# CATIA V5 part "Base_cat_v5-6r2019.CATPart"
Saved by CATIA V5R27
Part number: Base
Bounding box of the stored display mesh (mm): x -32 to 32, y 0 to 144, z 0 to 52
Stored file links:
  E:\_Deepak\2017_Deepak\CATIA\Resources\Tutorial Files\Tutorials\c16_catia_v5_6r2016_tut\Bench vice\Base_cat_v5-6r2016.CATPart
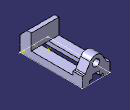
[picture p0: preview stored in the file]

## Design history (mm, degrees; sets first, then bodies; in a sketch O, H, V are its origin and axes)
Body1 (main body)
  Sketch1 on xy-plane, origin (0, 0, 0), H (1, 0, 0), V (0, 1, 0)
    point P1 (-32, 0)
    line L1 (-32, 0) -> (32, 0)
    line L2 (32, 0) -> (32, 144)
    line L3 (32, 144) -> (-32, 144)
    line L4 (-32, 144) -> (-32, 0)
    length L1 = 64
    length L2 = 144
    distance V L2 = 32
    coincidence: P1 H
    horizontal: L1 H, L3 H
    vertical: L2 V, L4 V
  Pad1: profile Sketch1, direction (0, 0, 1), length 16
  Sketch2 on face of Pad1, origin (32, 0, 0), H (0, 1, 0), V (0, 0, 1)
    point P1 (0, 16)
    line L1 (0, 16) -> (0, 36)
    point P2 (0, 36)
    line L2 (26, 52) -> (26, 16)
    line L3 (26, 16) -> (0, 16)
    reference projected line E1 (144, 16) -> (0, 16) from edge of Pad1
    line L4 (26, 52) -> (16, 52)
    point P5 (16, 52)
    line L5 (16, 52) -> (0, 36)
    length L2 = 36
    distance P5 P2 H = 16
    distance P5 P2 V = 16
    length L3 = 26
    coincidence: P1 V, E1 L3
    vertical: L1 V, L2 V
    horizontal: L3 H, L4 H
  Pad2: profile Sketch2, direction (-1, 0, 0), length 64
  Sketch3 on face of Pad1, origin (0, 144, 0), H (-1, 0, 0), V (0, 0, 1)
    line L1 (-32, 16) -> (-32, 24)
    point P2 (32, 24)
    line L2 (32, 24) -> (32, 16)
    line L3 (32, 16) -> (-32, 16)
    reference projected line E1 (32, 16) -> (-32, 16) from edge of Pad1
    line L4 (32, 24) -> (26, 24)
    point P4 (26, 24)
    line L5 (26, 24) -> (13.6777, 44.3018)
    point P5 (0, 52)
    line L6 (-13.6777, 44.3018) -> (-26, 24)
    point P6 (-26, 24)
    line L7 (-26, 24) -> (-32, 24)
    reference projected line E2 (32, 52) -> (-32, 52) from edge of Pad2
    reference projected line E3 (32, 16) -> (32, 52) from edge of Pad2
    reference projected line E4 (-32, 0) -> (-32, 16) from edge of Pad1
    arc A1 centre (0, 36) radius 16 from (13.6777, 44.3018) to (-13.6777, 44.3018) ccw
    point P8 (0, 36)
    reference projected line E5 (32, 52) -> (-32, 52) from edge of Pad2
    circle A2 centre (0, 36) radius 8
    distance H P2 = 24
    distance P6 P4 = 52
    distance P6 V = 26
    radius A1 = 16
    radius A2 = 8
    vertical: L1 V, L2 V
    horizontal: L3 H, L4 H, L7 H
    coincidence: L3 E1, P5 V, P6 L4, P5 E2, L2 E3, L1 E4, P8 V
    tangency: A1 E5, L6 A1, A1 L5
  Pad3: profile Sketch3, direction (0, -1, 0), length 22
  Fillet1: radius 3, on 2 edges
  Sketch4 on face of Pad1, origin (0, 144, 0), H (-1, 0, 0), V (0, 0, 1)
    point P1 (-16, 0)
    line L1 (-16, 0) -> (-16, 7)
    point P2 (-16, 7)
    line L2 (-16, 7) -> (-8, 7)
    point P3 (-8, 7)
    line L3 (-8, 7) -> (-8, 16)
    point P4 (-8, 16)
    line L4 (-8, 16) -> (0, 16)
    point P5 (0, 16)
    point P6 (16, 7)
    point P7 (16, 0)
    line L5 (16, 0) -> (16, 7)
    point P8 (8, 7)
    line L6 (16, 7) -> (8, 7)
    point P9 (8, 16)
    line L7 (8, 7) -> (8, 16)
    point P10 (0, 16)
    line L8 (8, 16) -> (0, 16)
    line L9 (-16, 0) -> (16, 0)
    point P11 (16, 0)
    distance L1 V = 16
    distance L3 V = 8
    distance H L4 = 16
    distance H L2 = 7
    coincidence: P1 H, P5 V, P7 P11, P5 P10
    vertical: L1 V, L3 V
    horizontal: L2 H, L4 H, L9 H
    symmetry: P2 P6 V, P1 P7 V, L1 L5 V, P3 P8 V, L2 L6 V, P4 P9 V, L3 L7 V, P5 P10 V, L4 L8 V
  Pocket1: profile Sketch4, direction (0, -1, 0), through (limit type 3)
  Sketch5 on face of Pad1, origin (0, 0, 0), H (1, 0, 0), V (0, -1, 0)
    circle A1 centre (22, -38) radius 3
    point P1 (22, -38)
    reference projected line E1 (32, 0) -> (-32, 0) from edge of Pad1
    radius A1 = 3
    distance P1 E1 = 38
    distance V P1 = 22
  Pocket2: profile Sketch5, direction (0, 0, 1), length 12
  RectPattern1: of Pocket2, direction 1 instances 2, spacing 70, along edge of Pad1, direction 2 instances 2, spacing 44, along edge of Pad1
